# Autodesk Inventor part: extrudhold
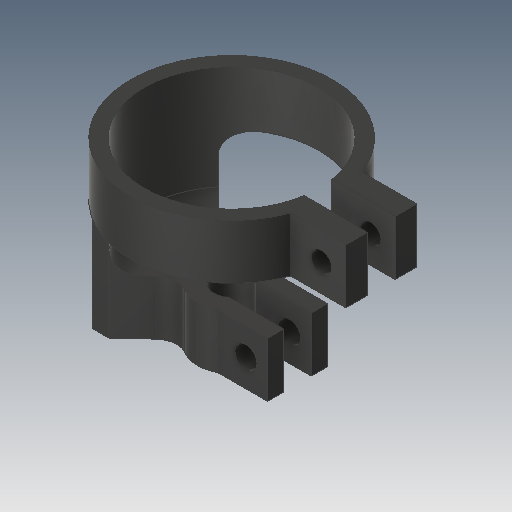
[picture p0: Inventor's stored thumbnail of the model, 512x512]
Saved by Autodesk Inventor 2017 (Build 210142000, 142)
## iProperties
Created: 2018-08
Part Number: extrudhold
Material: Plastic, Opaque Black
Document SubType Name: Modeling
Designer: JK
Density: 0.952 g/cm^3
Appearance: Smooth - Black
Author: JK
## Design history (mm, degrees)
sketch "Sketch1"
  geometry: C1 r 15.5 at (0, 0); C2 r 18.5 at (0, 0); 1 further point
  constraints: 2 centre point, 2 coincident
  dimensions: "d0" = 31 diameter of C1; "d1" = 37 diameter of C2
extrude "Extrusion1" new body sketch "Sketch1" distance "d2" = 10; taper "d3" = 0 deg
sketch "Sketch2"
  geometry: L1 (4.5, -14.832)-(4.5, -24); L2 (4.5, -24)-(-4.5, -24); L3 (-4.5, -24)-(-4.5, -14.832); L4 (4.5, 14.832)-(4.5, 24); L5 (4.5, 24)-(-4.5, 24); L6 (-4.5, 24)-(-4.5, 14.832); A1 r 15.5 centre (0, 0) between (-4.5, -14.832) and (-4.5, 14.832) reference; A2 r 15.5 centre (0, 0) between (-4.5, -14.832) and (4.5, -14.832); A3 r 15.5 centre (0, 0) between (4.5, 14.832) and (-4.5, 14.832); 1 further point
  constraints: 12 end point, 6 point on circle, 2 centre point, 2 parallel, 1 concentric, 1 point on line
  dimensions: "d4" = 9 distance between parallel lines of L1 L3; "d5" = 9 distance between parallel lines of L6 L4; "d6" = 4.5 distance from line of point (0, 0) L3; "d8" = 48 distance between parallel lines of L5 L2; "d9" = 24 distance from line of point (0, 0) L2
extrude "Extrusion2" join sketch "Sketch2" distance "d10" = 10; taper "d11" = 0 deg
sketch "Sketch3"
  geometry: C1 r 1.85 at (0, -19.25); C2 r 1.85 at (0, 19.25); 1 further point
  constraints: 2 centre point
  dimensions: "d12" = 3.7 diameter of C1; "d13" = 38.5 distance of C2.centre C1.centre; "d14" = 19.25 distance of point (0, 0) C1.centre
extrude "Extrusion3" cut sketch "Sketch3" distance "d15" = 10; taper "d16" = 0 deg
sketch "Sketch5"
  geometry: L1 (-4.5, -17.944)-(-4.5, -24) reference; L2 (-4.5, -17.944)-(-4.5, -14.832); L3 (-4.5, 17.944)-(-4.5, 14.832); A1 r 15.5 centre (0, 0) between (-4.5, 14.832) and (-4.5, -14.832); A2 r 18.5 centre (0, 0) between (-4.5, 17.944) and (-4.5, -17.944); A3 r 18.5 centre (0, 0) between (-4.5, 17.944) and (-4.5, -17.944) reference; 2 further points
  constraints: 4 end point, 4 point on circle, 2 centre point, 2 coincident, 1 collinear, 1 vertical, 2 other
extrude "Extrusion4" join sketch "Sketch5" distance "d19" = 15; taper "d20" = 0 deg
sketch "Sketch6"
  geometry: C1 r 15.5 at (0, 0); C2 r 18.5 at (0, 0); A1 r 15.5 centre (0, 0) between (-4.5, 14.832) and (-4.5, -14.832) reference; 1 further point
  constraints: 2 centre point, 1 coincident, 1 concentric
  dimensions: "d21" = 31 diameter of C1
extrude "Extrusion5" join sketch "Sketch6" distance "d22" = 10; taper "d23" = 0 deg
sketch "Sketch7"
  geometry: L1 (5.524, -1.5)-(22.142, -1.5); L2 (22.142, -1.5)-(22.142, 1.5); L3 (22.142, 1.5)-(5.524, 1.5); L4 (5.524, 1.5)-(5.524, -1.5); 1 further point
  constraints: 8 end point, 2 parallel, 1 horizontal, 1 perpendicular
  dimensions: "d24" = 3 distance of L3.end L1.start; "d25" = 1.5 distance from line of point (0, 0) L1
extrude "Extrusion6" cut sketch "Sketch7" distance "d26" = 12.25; taper "d27" = 0 deg
sketch "Sketch8"
  geometry: L1 (15.427, -1.5)-(27.427, -1.5); L2 (27.427, -1.5)-(27.427, -6.5); L3 (27.427, -6.5)-(15.427, -6.5); L4 (15.427, -6.5)-(15.427, -1.5); L5 (18.439, 1.5)-(15.427, 1.5) reference; L6 (15.427, 1.5)-(27.427, 1.5); L7 (27.427, 1.5)-(27.427, 6.5); L8 (27.427, 6.5)-(15.427, 6.5); L9 (15.427, 6.5)-(15.427, 1.5); 1 further point
  constraints: 16 end point, 4 parallel, 2 horizontal, 2 perpendicular, 1 collinear
  dimensions: "d28" = 5 distance between parallel lines of L1 L3; "d29" = 5 distance between parallel lines of L8 L6; "d30" = 12 distance of L7.end L8.end
extrude "Extrusion7" join sketch "Sketch8" distance "d31" = 10; taper "d32" = 0 deg
sketch "Sketch9"
  geometry: L1 (10.107, 0)-(10.107, -10) reference; L2 (10.107, 0)-(0, 0) reference; C1 r 1.85 at (5.607, -5); 1 further point
  constraints: 1 centre point
  dimensions: "d33" = 3.7 diameter of C1; "d34" = 4.5 distance from line of L1 C1.centre; "d35" = 5 distance from line of L2 C1.centre
extrude "Extrusion8" cut sketch "Sketch9" distance "d36" = 24.5; taper "d37" = 0 deg
sketch "Sketch10"
  geometry: L1 (27.427, -1.5)-(27.427, -6.5) reference; L2 (27.427, -2.5)-(12.843, -2.5); L3 (12.843, -2.5)-(12.843, 2.5); L4 (12.843, 2.5)-(27.427, 2.5); L5 (27.427, 2.5)-(27.427, -2.5); L6 (27.427, -1.5)-(15.427, -1.5) reference; L7 (15.427, 1.5)-(27.427, 1.5) reference; 1 further point
  constraints: 8 end point, 2 parallel, 1 horizontal, 1 perpendicular, 1 point on line
  dimensions: "d38" = 1 distance between parallel lines of L6 L2; "d39" = 1 distance between parallel lines of L7 L4
extrude "Extrusion9" cut sketch "Sketch10" distance "d40" = 11.5; taper "d41" = 0 deg
sketch "Sketch11"
  geometry: C1 r 16 at (0, 0); 1 further point
  constraints: 1 centre point, 1 coincident
  dimensions: "d42" = 32 diameter of C1
extrude "Extrusion10" cut sketch "Sketch11" distance "d43" = 59.25; taper "d44" = 0 deg
sketch "Sketch12"
  geometry: C1 r 30.735 at (0, 0); 1 further point
  constraints: 1 centre point, 1 coincident
extrude "Extrusion11" cut sketch "Sketch12" stored distance "d45" = 10; taper "d46" = 0 deg
sketch "Sketch15"
  geometry: L1 (-12.49, -10)-(-21.942, -10); L2 (-21.942, -10)-(-21.942, 10); L3 (-21.942, 10)-(-12.49, 10); L4 (-13.041, -5.012)-(-21.942, 10); L5 (-21.942, -10)-(-17.743, -2.948); A1 r 18.5 centre (0, 0) between (17.321, 6.5) and (17.321, -6.5) reference; A2 r 16 centre (0, 0) between (-12.49, 10) and (-12.49, -10); A3 r 16 centre (0, 0) between (15.803, 2.5) and (15.803, -2.5) reference; A4 r 18.5 centre (0, 0) between (-15.564, 10) and (-15.564, -10); 2 further points
  constraints: 10 end point, 8 point on circle, 5 point on line, 2 centre point, 2 coincident, 1 concentric, 1 horizontal, 1 parallel, 1 perpendicular
  dimensions: "d48" = 20 distance of L1.end L2.end; "d64" = 10 distance from line of A1.centre L1
extrude "Extrusion12" join sketch "Sketch15" distance "d49" = 13; taper "d50" = 0 deg
sketch "Sketch16"
  geometry: L1 (17.27, -10)-(-15.564, -10); L2 (-15.564, -10)-(-15.564, 10); L3 (-15.564, 10)-(17.27, 10); L4 (17.27, 10)-(17.27, -10); L5 (17.27, -10)-(-15.564, 10); L6 (-15.564, -10)-(17.27, 10); A1 r 18.5 centre (0, 0) between (-15.564, 10) and (-15.564, -10) reference; A2 r 18.5 centre (-0.052, 0.08) between (-15.564, 10.16) and (-15.564, -10); 2 further points
  constraints: 12 end point, 2 coincident, 2 midpoint, 2 parallel, 2 point on circle, 1 centre point, 1 horizontal, 1 perpendicular
  dimensions: "d53" = 20 distance of L1.end L2.end
extrude "Extrusion13" join sketch "Sketch16" distance "d54" = 10; taper "d55" = 0 deg
sketch "Sketch18"
  geometry: C1 r 3.25 at (0, 0); 1 further point
  constraints: 1 centre point, 1 coincident
  dimensions: "d58" = 6.5 diameter of C1
extrude "Extrusion15" cut sketch "Sketch18" distance "d59" = 66.75; taper "d60" = 0 deg
sketch "Sketch19"
  geometry: L1 (0, 6.25)-(-12.49, 10); L2 (-12.49, 10)-(21.536, 21.862); L3 (21.536, 21.862)-(23.48, -17.523); L4 (23.48, -17.523)-(4.491, -14.779); L5 (4.491, -14.779)-(-12.49, -10); L6 (-12.49, -10)-(0, -6.25); L7 (17.27, 10)-(-15.564, 10) reference; L8 (-15.564, -10)-(17.27, -10) reference; C1 r 3.25 at (0, 0) reference; A1 r 6.25 centre (0, 0) between (0, 6.25) and (0, -6.25); A2 r 16 centre (0, 0) between (-12.49, -10) and (15.803, -2.5) reference; 1 further point
  constraints: 12 end point, 3 point on circle, 2 point on line, 1 centre point, 1 coincident, 1 vertical alignment
  dimensions: "d61" = 3 radial gap between concentric circles of A1 C1
extrude "Extrusion16" cut sketch "Sketch19" distance "d62" = 10; taper "d63" = 0 deg
sketch "Sketch21"
  geometry: L1 (-12.49, 10)-(-15.564, 10) reference; L2 (-15.564, -10)-(-15.564, -3.708) reference; L3 (-15.564, -10)-(-15.564, 10); A1 r 18.5 centre (0, 0) between (-15.564, 10) and (-15.564, -10); 1 further point
  constraints: 2 end point, 2 point on circle, 1 centre point, 1 vertical
extrude "Extrusion17" join sketch "Sketch21" distance "d65" = 10; taper "d66" = 0 deg
sketch "Sketch22"
  geometry: L1 (10.937, -2.5)-(1.563, -2.5); L2 (1.563, -2.5)-(1.563, 2.5); L3 (1.563, 2.5)-(10.937, 2.5); L4 (10.937, 2.5)-(10.937, -2.5); L5 (10.937, -2.5)-(1.563, 2.5); L6 (1.563, -2.5)-(10.937, 2.5); A1 r 6.25 centre (0, 0) between (0, -6.25) and (0, 6.25) reference; 2 further points
  constraints: 12 end point, 2 midpoint, 2 parallel, 1 horizontal, 1 perpendicular, 1 point on circle
  dimensions: "d67" = 5 distance of L1.end L2.end
extrude "Extrusion18" cut sketch "Sketch22" distance "d68" = 13.25; taper "d69" = 0 deg
sketch "Sketch23"
  geometry: L1 (2.077, -2.5)-(12.077, -2.5); L2 (12.077, -2.5)-(12.077, -5.5); L3 (12.077, -5.5)-(2.077, -5.5); L4 (2.077, -5.5)-(2.077, -2.5); L5 (2.077, 2.5)-(5.728, 2.5) reference; L6 (2.077, 2.5)-(12.077, 2.5); L7 (12.077, 2.5)-(12.077, 5.5); L8 (12.077, 5.5)-(2.077, 5.5); L9 (2.077, 5.5)-(2.077, 2.5); A1 r 3.25 centre (0, 0) between (2.077, 2.5) and (2.077, -2.5) reference; 1 further point
  constraints: 16 end point, 4 parallel, 2 horizontal, 2 perpendicular, 1 collinear
  dimensions: "d70" = 3 distance of L1.end L2.end; "d71" = 3 distance of L6.end L7.end; "d72" = 10 distance of L2.end L3.end
extrude "Extrusion19" join sketch "Sketch23" distance "d73" = 10; taper "d74" = 0 deg
sketch "Sketch24"
  geometry: L1 (9.108, 0)-(9.108, 10) reference; C1 r 2 at (5.108, 5); 1 further point
  constraints: 1 centre point
  dimensions: "d75" = 4 diameter of C1; "d76" = 4 distance from line of L1 C1.centre
extrude "Extrusion20" cut sketch "Sketch24" distance "d77" = 17.75; taper "d78" = 0 deg
sketch "Sketch25"
  geometry: L1 (-12.49, -10)-(0, -6.25) reference; L2 (-12.49, 10)-(-5.288, 3.311); L3 (-5.288, -3.311)-(-12.49, -10); L4 (0, -6.25)-(-12.49, -10); L5 (-12.49, 10)-(0, 6.25) reference; L6 (-12.49, 10)-(0, 6.25); A1 r 6.25 centre (0, 0) between (0, -6.25) and (2.969, -5.5) reference; A2 r 6.25 centre (0, 0) between (2.969, 5.5) and (0, 6.25) reference; A3 r 16 centre (0, 0) between (15.803, 2.5) and (-12.49, 10) reference; A4 r 6.25 centre (0.013, 0) between (-5.288, -3.311) and (0.013, -6.25); A5 r 6.25 centre (0.013, 0) between (0, 6.25) and (-5.288, 3.311); 1 further point
  constraints: 8 end point, 6 point on circle, 2 centre point, 2 collinear, 1 equal length
extrude "Extrusion22" cut sketch "Sketch25" distance "d81" = 17.75; taper "d82" = 0 deg
fillet "Fillet1" dims "d83" = 4
body "Solid1"
